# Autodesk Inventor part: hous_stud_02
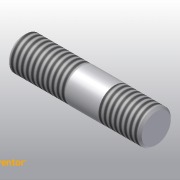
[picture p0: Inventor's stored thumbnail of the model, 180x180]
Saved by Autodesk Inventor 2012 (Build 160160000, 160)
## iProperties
Shininess: 64.0
Length Units: 11272
Angle Units: 11279
Time Units: 11290
Mass Units: 11286
Length Display Precision: 3
Angle Display Precision: 2
Compacted: True
Company: Autodesk
Created: 2002-07
Part Number: hous_stud_02
Document SubType Name: Modeling
Designer: Lieven Grauls
Stock Number: hous_stud_02
Project: Valve Techcamp 2008
Density: 1 g/cm^3
Mass: 6.44343 g
Surface Area: 22.516 cm^2
Volume: 6.44343 cm^3
Material: Default
Density: 0.0
Volumn: 0.0
Area: 0.0
PropertySet Name: Model Information
Control State: 0
Master: False
Checked Out: False
Author: Lieven Grauls
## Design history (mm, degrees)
sketch "Sketch1"
  geometry: L1 (0, 0)-(0, 6.35); L2 (0, 6.35)-(22.225, 6.35); L3 (22.225, 6.35)-(22.225, 6.414); L4 (22.225, 6.414)-(34.925, 6.414); L5 (34.925, 6.414)-(34.925, 6.35); L6 (34.925, 6.35)-(50.8, 6.35); L7 (50.8, 6.35)-(50.8, 0); L8 (50.8, 0)-(0, 0)
  constraints: 16 end point, 5 parallel, 2 collinear, 1 perpendicular, 1 vertical
  dimensions: "d0" = 12.7 diameter of L2 L8; "d1" = 12.827 diameter of L4 L8; "d2" = 22.225 distance of L1.end L2.end; "d3" = 15.875 distance of L5.end L6.end; "d4" = 50.8 distance between parallel lines of L7 L1
revolve "Revolution1" sketch "Sketch1" stored, may be unused: angle "d5" = 90 deg
thread "Thread1" dims "d6" = 25.4, "d7" = 0
thread "Thread2" dims "d8" = 25.4, "d9" = 0
chamfer "Chamfer1" distance "d10" = 0.79375; stored, may be unused: second distance "d11" = 0.79375, angle "d12" = 45 deg
node "Volumenkörper1"
node "Volumenkörpern"
node "Oberflächenkörpern"
